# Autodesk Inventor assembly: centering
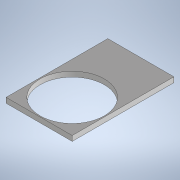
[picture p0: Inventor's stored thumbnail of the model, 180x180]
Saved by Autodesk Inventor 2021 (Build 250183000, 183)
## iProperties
Created: 2026-10
Part Number: centering
Document SubType Name: Assembly
Designer: alolo
Author: alolo
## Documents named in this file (2)
- C:\Users\hp\Documents\Inventor\DOM1_CartesianRobot\centering.iam
- C:\Users\hp\Documents\Inventor\DOM1_CartesianRobot\centering_bore.ipt
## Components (1 placed, 1 different names)
1. centering_bore:1
